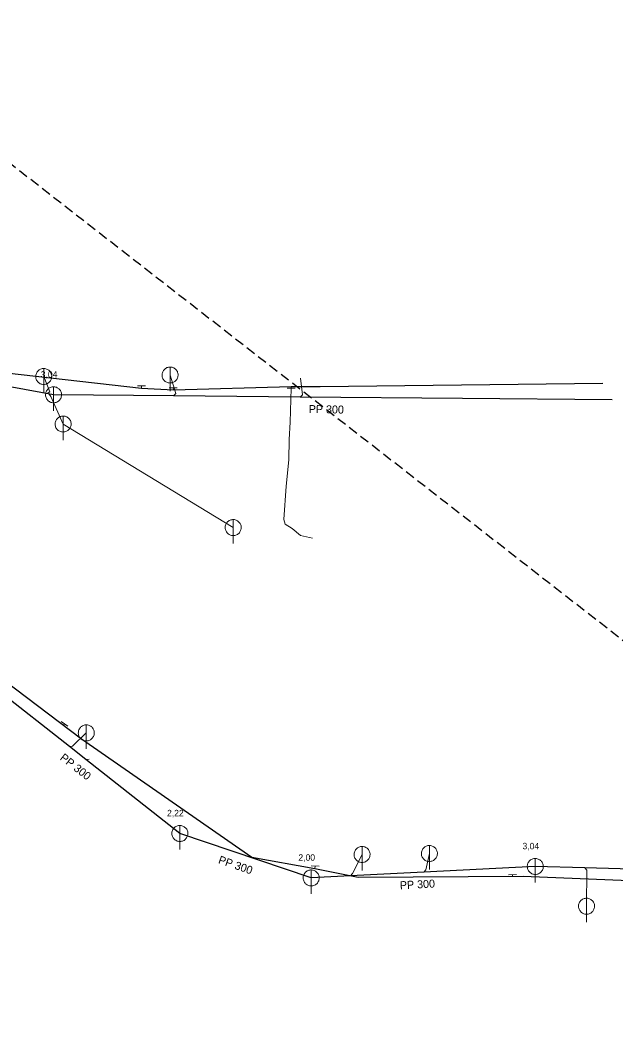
# Model space of a CAD drawing. Extents: x -683466 to -682479, y -996772 to -995963.
# Drawn here: x -683311.7 to -683237.4, y -996087.9 to -995963.2 of the extents above; entities that cross this region are included whole.
import ezdxf

# ---------------------------------------------------------------- set-up
doc = ezdxf.new("R2010")
doc.units = 0
doc.header["$LTSCALE"] = 0.4
doc.linetypes.add('MEDIUM_DASHED', pattern=[4.5, 3, -1.5])
doc.layers.add('1', color=7, linetype='Continuous')
for name, color, linetype, lineweight in [('11', 7, 'Continuous', 13), ('13', 7, 'Continuous', 13), ('14', 7, 'Continuous', 25), ('17', 7, 'Continuous', 25), ('22', 7, 'Continuous', 13), ('34', 7, 'Continuous', 13), ('63', 7, 'MEDIUM_DASHED', 25)]:
    doc.layers.add(name, color=color, linetype=linetype, lineweight=lineweight)

msp = doc.modelspace()

# ---------------------------------------------------------------- linework, layer by layer
at = {"layer": '11'}
msp.add_line((-683285.12, -996026.62), (-683306.359, -996013.69), dxfattribs=at)
for points in [[(-683308.78, -996007.75), (-683308.009, -996009.668), (-683308.342, -996009.895)], [(-683293, -996007.57), (-683292.302, -996009.895), (-683292.588, -996010.175)], [(-683276.719, -996007.96), (-683276.463, -996010.037), (-683276.748, -996010.318)], [(-683306.359, -996013.69), (-683307.879, -996010.27), (-683308.102, -996009.939)], [(-683303.46, -996052.26), (-683305.175, -996053.934), (-683305.57, -996053.982)], [(-683303.109, -996055.561), (-683303.398, -996055.596), (-683303.509, -996055.596)], [(-683269.03, -996067.449), (-683270.223, -996069.84), (-683270.486, -996070.129)], [(-683260.62, -996067.329), (-683261.046, -996069.37), (-683261.307, -996069.66)], [(-683241, -996073.91), (-683240.945, -996069.41), (-683241.213, -996069.127)]]:
    msp.add_lwpolyline(points, dxfattribs=at)
at = {"layer": '13'}
msp.add_lwpolyline([(-683277.891, -996009.221), (-683277.998, -996013.465), (-683278.128, -996015.609), (-683278.178, -996018.154), (-683278.489, -996021.447), (-683278.813, -996025.612), (-683278.612, -996026.183), (-683277.741, -996026.737), (-683276.712, -996027.626), (-683275.231, -996027.926)], dxfattribs=at)
at = {"layer": '14', "lineweight": 13}
for p, q in [((-683296.567, -996009.217), (-683296.559, -996008.92)), ((-683292.577, -996009.418), (-683292.609, -996009.16)), ((-683277.891, -996009.221), (-683277.891, -996009.01)), ((-683306.313, -996051.309), (-683306.18, -996051.12)), ((-683274.899, -996068.89), (-683274.905, -996069.189)), ((-683250.223, -996070.173), (-683250.23, -996069.98))]:
    msp.add_line(p, q, dxfattribs=at)
at = {"layer": '14'}
msp.add_line((-683275.379, -996070.379), (-683291.78, -996064.829), dxfattribs=at)
for points in [[(-683307.55, -996010.039), (-683324.795, -996006.888), (-683328.719, -996006.171), (-683331.359, -996005.69)], [(-683237.8, -996010.67), (-683256.469, -996010.5), (-683276.748, -996010.318), (-683292.588, -996010.175), (-683307.55, -996010.039)], [(-683291.78, -996064.829), (-683303.509, -996055.596), (-683305.57, -996053.982), (-683314.71, -996046.82)], [(-683247.399, -996068.949), (-683261.307, -996069.66), (-683270.486, -996070.129), (-683275.379, -996070.379)], [(-683215.92, -996069.85), (-683225.026, -996069.59), (-683241.213, -996069.127), (-683247.399, -996068.949)]]:
    msp.add_lwpolyline(points, dxfattribs=at)
at = {"layer": '17'}
for points in [[(-683345.871, -996001.145), (-683330.998, -996004.133), (-683319.329, -996006.62), (-683296.567, -996009.217), (-683292.577, -996009.418), (-683277.891, -996009.01), (-683274.249, -996009.008), (-683238.954, -996008.579)], [(-683345.87, -996001.27), (-683340.96, -996022.3), (-683339.832, -996025.943), (-683304.056, -996053.017), (-683282.79, -996067.766), (-683274.905, -996069.189), (-683269.5, -996070.27), (-683248.91, -996070.167), (-683229.542, -996070.96), (-683219.888, -996069.96)]]:
    msp.add_lwpolyline(points, dxfattribs=at)
at = {"layer": '22'}
for p, q in [((-683308.78, -996009.75), (-683308.779, -996006.75)), ((-683293, -996009.57), (-683292.999, -996006.57)), ((-683307.55, -996012.039), (-683307.549, -996009.039)), ((-683306.359, -996015.69), (-683306.358, -996012.69)), ((-683285.12, -996028.62), (-683285.119, -996025.62)), ((-683303.46, -996054.26), (-683303.459, -996051.26)), ((-683291.78, -996066.829), (-683291.779, -996063.829)), ((-683269.03, -996069.449), (-683269.029, -996066.449)), ((-683260.62, -996069.329), (-683260.619, -996066.329)), ((-683247.399, -996070.949), (-683247.398, -996067.949)), ((-683275.379, -996072.379), (-683275.378, -996069.379)), ((-683241, -996075.91), (-683240.999, -996072.91))]:
    msp.add_line(p, q, dxfattribs=at)
for points in [[(-683307.78, -996007.75), (-683307.785, -996007.641), (-683307.803, -996007.533), (-683307.833, -996007.427), (-683307.873, -996007.326), (-683307.925, -996007.229), (-683307.987, -996007.139), (-683308.059, -996007.056), (-683308.139, -996006.982), (-683308.227, -996006.916), (-683308.321, -996006.861), (-683308.421, -996006.816), (-683308.526, -996006.783), (-683308.633, -996006.761), (-683308.742, -996006.751), (-683308.852, -996006.753), (-683308.96, -996006.767), (-683309.067, -996006.792), (-683309.17, -996006.829), (-683309.268, -996006.878), (-683309.36, -996006.936), (-683309.446, -996007.005), (-683309.523, -996007.082), (-683309.592, -996007.168), (-683309.651, -996007.26), (-683309.699, -996007.358), (-683309.736, -996007.461), (-683309.762, -996007.568), (-683309.776, -996007.676), (-683309.779, -996007.786), (-683309.769, -996007.895), (-683309.748, -996008.002), (-683309.714, -996008.106), (-683309.67, -996008.206), (-683309.615, -996008.301), (-683309.549, -996008.389), (-683309.475, -996008.469), (-683309.392, -996008.541), (-683309.302, -996008.603), (-683309.206, -996008.655), (-683309.104, -996008.696), (-683308.999, -996008.726), (-683308.891, -996008.744), (-683308.781, -996008.75), (-683308.672, -996008.744), (-683308.564, -996008.726), (-683308.459, -996008.697), (-683308.357, -996008.656), (-683308.26, -996008.604), (-683308.17, -996008.542), (-683308.087, -996008.471), (-683308.012, -996008.391), (-683307.947, -996008.303), (-683307.891, -996008.209), (-683307.847, -996008.109), (-683307.813, -996008.005), (-683307.791, -996007.897), (-683307.781, -996007.788)], [(-683292, -996007.57), (-683292.005, -996007.461), (-683292.023, -996007.353), (-683292.053, -996007.247), (-683292.093, -996007.146), (-683292.145, -996007.049), (-683292.207, -996006.959), (-683292.279, -996006.876), (-683292.359, -996006.802), (-683292.447, -996006.736), (-683292.541, -996006.681), (-683292.641, -996006.636), (-683292.746, -996006.603), (-683292.853, -996006.581), (-683292.962, -996006.571), (-683293.072, -996006.573), (-683293.18, -996006.587), (-683293.287, -996006.612), (-683293.39, -996006.649), (-683293.488, -996006.698), (-683293.58, -996006.756), (-683293.666, -996006.825), (-683293.743, -996006.902), (-683293.812, -996006.988), (-683293.871, -996007.08), (-683293.919, -996007.178), (-683293.956, -996007.281), (-683293.982, -996007.388), (-683293.996, -996007.496), (-683293.999, -996007.606), (-683293.989, -996007.715), (-683293.968, -996007.822), (-683293.934, -996007.926), (-683293.89, -996008.026), (-683293.835, -996008.121), (-683293.769, -996008.209), (-683293.695, -996008.289), (-683293.612, -996008.361), (-683293.522, -996008.423), (-683293.426, -996008.475), (-683293.324, -996008.516), (-683293.219, -996008.546), (-683293.111, -996008.564), (-683293.001, -996008.57), (-683292.892, -996008.564), (-683292.784, -996008.546), (-683292.679, -996008.517), (-683292.577, -996008.476), (-683292.48, -996008.424), (-683292.39, -996008.362), (-683292.307, -996008.291), (-683292.232, -996008.211), (-683292.167, -996008.123), (-683292.111, -996008.029), (-683292.067, -996007.929), (-683292.033, -996007.825), (-683292.011, -996007.717), (-683292.001, -996007.608)], [(-683306.55, -996010.039), (-683306.555, -996009.93), (-683306.573, -996009.822), (-683306.603, -996009.716), (-683306.643, -996009.615), (-683306.695, -996009.518), (-683306.757, -996009.428), (-683306.829, -996009.345), (-683306.909, -996009.271), (-683306.997, -996009.205), (-683307.091, -996009.15), (-683307.191, -996009.105), (-683307.296, -996009.072), (-683307.403, -996009.05), (-683307.512, -996009.04), (-683307.622, -996009.042), (-683307.73, -996009.056), (-683307.837, -996009.081), (-683307.94, -996009.118), (-683308.038, -996009.167), (-683308.13, -996009.225), (-683308.216, -996009.294), (-683308.293, -996009.371), (-683308.362, -996009.457), (-683308.421, -996009.549), (-683308.469, -996009.647), (-683308.506, -996009.75), (-683308.532, -996009.857), (-683308.546, -996009.965), (-683308.549, -996010.075), (-683308.539, -996010.184), (-683308.518, -996010.291), (-683308.484, -996010.395), (-683308.44, -996010.495), (-683308.385, -996010.59), (-683308.319, -996010.678), (-683308.245, -996010.758), (-683308.162, -996010.83), (-683308.072, -996010.892), (-683307.976, -996010.944), (-683307.874, -996010.985), (-683307.769, -996011.015), (-683307.661, -996011.033), (-683307.551, -996011.039), (-683307.442, -996011.033), (-683307.334, -996011.015), (-683307.229, -996010.986), (-683307.127, -996010.945), (-683307.03, -996010.893), (-683306.94, -996010.831), (-683306.857, -996010.76), (-683306.782, -996010.68), (-683306.717, -996010.592), (-683306.661, -996010.498), (-683306.617, -996010.398), (-683306.583, -996010.294), (-683306.561, -996010.186), (-683306.551, -996010.077)], [(-683305.359, -996013.69), (-683305.364, -996013.581), (-683305.382, -996013.473), (-683305.412, -996013.367), (-683305.452, -996013.266), (-683305.504, -996013.169), (-683305.566, -996013.079), (-683305.638, -996012.996), (-683305.718, -996012.922), (-683305.806, -996012.856), (-683305.9, -996012.801), (-683306, -996012.756), (-683306.105, -996012.723), (-683306.212, -996012.701), (-683306.321, -996012.691), (-683306.431, -996012.693), (-683306.539, -996012.707), (-683306.646, -996012.732), (-683306.749, -996012.769), (-683306.847, -996012.818), (-683306.939, -996012.876), (-683307.025, -996012.945), (-683307.102, -996013.022), (-683307.171, -996013.108), (-683307.23, -996013.2), (-683307.278, -996013.298), (-683307.315, -996013.401), (-683307.341, -996013.508), (-683307.355, -996013.616), (-683307.358, -996013.726), (-683307.348, -996013.835), (-683307.327, -996013.942), (-683307.293, -996014.046), (-683307.249, -996014.146), (-683307.194, -996014.241), (-683307.128, -996014.329), (-683307.054, -996014.409), (-683306.971, -996014.481), (-683306.881, -996014.543), (-683306.785, -996014.595), (-683306.683, -996014.636), (-683306.578, -996014.666), (-683306.47, -996014.684), (-683306.36, -996014.69), (-683306.251, -996014.684), (-683306.143, -996014.666), (-683306.038, -996014.637), (-683305.936, -996014.596), (-683305.839, -996014.544), (-683305.749, -996014.482), (-683305.666, -996014.411), (-683305.591, -996014.331), (-683305.526, -996014.243), (-683305.47, -996014.149), (-683305.426, -996014.049), (-683305.392, -996013.945), (-683305.37, -996013.837), (-683305.36, -996013.728)], [(-683284.12, -996026.62), (-683284.125, -996026.511), (-683284.143, -996026.403), (-683284.173, -996026.297), (-683284.213, -996026.196), (-683284.265, -996026.099), (-683284.327, -996026.009), (-683284.399, -996025.926), (-683284.479, -996025.852), (-683284.567, -996025.786), (-683284.661, -996025.731), (-683284.761, -996025.686), (-683284.866, -996025.653), (-683284.973, -996025.631), (-683285.082, -996025.621), (-683285.192, -996025.623), (-683285.3, -996025.637), (-683285.407, -996025.662), (-683285.51, -996025.699), (-683285.608, -996025.748), (-683285.7, -996025.806), (-683285.786, -996025.875), (-683285.863, -996025.952), (-683285.932, -996026.038), (-683285.991, -996026.13), (-683286.039, -996026.228), (-683286.076, -996026.331), (-683286.102, -996026.438), (-683286.116, -996026.546), (-683286.119, -996026.656), (-683286.109, -996026.765), (-683286.088, -996026.872), (-683286.054, -996026.976), (-683286.01, -996027.076), (-683285.955, -996027.171), (-683285.889, -996027.259), (-683285.815, -996027.339), (-683285.732, -996027.411), (-683285.642, -996027.473), (-683285.546, -996027.525), (-683285.444, -996027.566), (-683285.339, -996027.596), (-683285.231, -996027.614), (-683285.121, -996027.62), (-683285.012, -996027.614), (-683284.904, -996027.596), (-683284.799, -996027.567), (-683284.697, -996027.526), (-683284.6, -996027.474), (-683284.51, -996027.412), (-683284.427, -996027.341), (-683284.352, -996027.261), (-683284.287, -996027.173), (-683284.231, -996027.079), (-683284.187, -996026.979), (-683284.153, -996026.875), (-683284.131, -996026.767), (-683284.121, -996026.658)], [(-683302.46, -996052.26), (-683302.465, -996052.151), (-683302.483, -996052.043), (-683302.513, -996051.937), (-683302.553, -996051.836), (-683302.605, -996051.739), (-683302.667, -996051.649), (-683302.739, -996051.566), (-683302.819, -996051.492), (-683302.907, -996051.426), (-683303.001, -996051.371), (-683303.101, -996051.326), (-683303.206, -996051.293), (-683303.313, -996051.271), (-683303.422, -996051.261), (-683303.532, -996051.263), (-683303.64, -996051.277), (-683303.747, -996051.302), (-683303.85, -996051.339), (-683303.948, -996051.388), (-683304.04, -996051.446), (-683304.126, -996051.515), (-683304.203, -996051.592), (-683304.272, -996051.678), (-683304.331, -996051.77), (-683304.379, -996051.868), (-683304.416, -996051.971), (-683304.442, -996052.078), (-683304.456, -996052.186), (-683304.459, -996052.296), (-683304.449, -996052.405), (-683304.428, -996052.512), (-683304.394, -996052.616), (-683304.35, -996052.716), (-683304.295, -996052.811), (-683304.229, -996052.899), (-683304.155, -996052.979), (-683304.072, -996053.051), (-683303.982, -996053.113), (-683303.886, -996053.165), (-683303.784, -996053.206), (-683303.679, -996053.236), (-683303.571, -996053.254), (-683303.461, -996053.26), (-683303.352, -996053.254), (-683303.244, -996053.236), (-683303.139, -996053.207), (-683303.037, -996053.166), (-683302.94, -996053.114), (-683302.85, -996053.052), (-683302.767, -996052.981), (-683302.692, -996052.901), (-683302.627, -996052.813), (-683302.571, -996052.719), (-683302.527, -996052.619), (-683302.493, -996052.515), (-683302.471, -996052.407), (-683302.461, -996052.298)], [(-683290.78, -996064.829), (-683290.785, -996064.72), (-683290.803, -996064.612), (-683290.833, -996064.506), (-683290.873, -996064.405), (-683290.925, -996064.308), (-683290.987, -996064.218), (-683291.059, -996064.135), (-683291.139, -996064.061), (-683291.227, -996063.995), (-683291.321, -996063.94), (-683291.421, -996063.895), (-683291.526, -996063.862), (-683291.633, -996063.84), (-683291.742, -996063.83), (-683291.852, -996063.832), (-683291.96, -996063.846), (-683292.067, -996063.871), (-683292.17, -996063.908), (-683292.268, -996063.957), (-683292.36, -996064.015), (-683292.446, -996064.084), (-683292.523, -996064.161), (-683292.592, -996064.247), (-683292.651, -996064.339), (-683292.699, -996064.437), (-683292.736, -996064.54), (-683292.762, -996064.647), (-683292.776, -996064.755), (-683292.779, -996064.865), (-683292.769, -996064.974), (-683292.748, -996065.081), (-683292.714, -996065.185), (-683292.67, -996065.285), (-683292.615, -996065.38), (-683292.549, -996065.468), (-683292.475, -996065.548), (-683292.392, -996065.62), (-683292.302, -996065.682), (-683292.206, -996065.734), (-683292.104, -996065.775), (-683291.999, -996065.805), (-683291.891, -996065.823), (-683291.781, -996065.829), (-683291.672, -996065.823), (-683291.564, -996065.805), (-683291.459, -996065.776), (-683291.357, -996065.735), (-683291.26, -996065.683), (-683291.17, -996065.621), (-683291.087, -996065.55), (-683291.012, -996065.47), (-683290.947, -996065.382), (-683290.891, -996065.288), (-683290.847, -996065.188), (-683290.813, -996065.084), (-683290.791, -996064.976), (-683290.781, -996064.867)], [(-683268.03, -996067.449), (-683268.035, -996067.34), (-683268.053, -996067.232), (-683268.083, -996067.126), (-683268.123, -996067.025), (-683268.175, -996066.928), (-683268.237, -996066.838), (-683268.309, -996066.755), (-683268.389, -996066.681), (-683268.477, -996066.615), (-683268.571, -996066.56), (-683268.671, -996066.515), (-683268.776, -996066.482), (-683268.883, -996066.46), (-683268.992, -996066.45), (-683269.102, -996066.452), (-683269.21, -996066.466), (-683269.317, -996066.491), (-683269.42, -996066.528), (-683269.518, -996066.577), (-683269.61, -996066.635), (-683269.696, -996066.704), (-683269.773, -996066.781), (-683269.842, -996066.867), (-683269.901, -996066.959), (-683269.949, -996067.057), (-683269.986, -996067.16), (-683270.012, -996067.267), (-683270.026, -996067.375), (-683270.029, -996067.485), (-683270.019, -996067.594), (-683269.998, -996067.701), (-683269.964, -996067.805), (-683269.92, -996067.905), (-683269.865, -996068), (-683269.799, -996068.088), (-683269.725, -996068.168), (-683269.642, -996068.24), (-683269.552, -996068.302), (-683269.456, -996068.354), (-683269.354, -996068.395), (-683269.249, -996068.425), (-683269.141, -996068.443), (-683269.031, -996068.449), (-683268.922, -996068.443), (-683268.814, -996068.425), (-683268.709, -996068.396), (-683268.607, -996068.355), (-683268.51, -996068.303), (-683268.42, -996068.241), (-683268.337, -996068.17), (-683268.262, -996068.09), (-683268.197, -996068.002), (-683268.141, -996067.908), (-683268.097, -996067.808), (-683268.063, -996067.704), (-683268.041, -996067.596), (-683268.031, -996067.487)], [(-683259.62, -996067.329), (-683259.625, -996067.22), (-683259.643, -996067.112), (-683259.673, -996067.006), (-683259.713, -996066.905), (-683259.765, -996066.808), (-683259.827, -996066.718), (-683259.899, -996066.635), (-683259.979, -996066.561), (-683260.067, -996066.495), (-683260.161, -996066.44), (-683260.261, -996066.395), (-683260.366, -996066.362), (-683260.473, -996066.34), (-683260.582, -996066.33), (-683260.692, -996066.332), (-683260.8, -996066.346), (-683260.907, -996066.371), (-683261.01, -996066.408), (-683261.108, -996066.457), (-683261.2, -996066.515), (-683261.286, -996066.584), (-683261.363, -996066.661), (-683261.432, -996066.747), (-683261.491, -996066.839), (-683261.539, -996066.937), (-683261.576, -996067.04), (-683261.602, -996067.147), (-683261.616, -996067.255), (-683261.619, -996067.365), (-683261.609, -996067.474), (-683261.588, -996067.581), (-683261.554, -996067.685), (-683261.51, -996067.785), (-683261.455, -996067.88), (-683261.389, -996067.968), (-683261.315, -996068.048), (-683261.232, -996068.12), (-683261.142, -996068.182), (-683261.046, -996068.234), (-683260.944, -996068.275), (-683260.839, -996068.305), (-683260.731, -996068.323), (-683260.621, -996068.329), (-683260.512, -996068.323), (-683260.404, -996068.305), (-683260.299, -996068.276), (-683260.197, -996068.235), (-683260.1, -996068.183), (-683260.01, -996068.121), (-683259.927, -996068.05), (-683259.852, -996067.97), (-683259.787, -996067.882), (-683259.731, -996067.788), (-683259.687, -996067.688), (-683259.653, -996067.584), (-683259.631, -996067.476), (-683259.621, -996067.367)], [(-683246.399, -996068.949), (-683246.404, -996068.84), (-683246.422, -996068.732), (-683246.452, -996068.626), (-683246.492, -996068.525), (-683246.544, -996068.428), (-683246.606, -996068.338), (-683246.678, -996068.255), (-683246.758, -996068.181), (-683246.846, -996068.115), (-683246.94, -996068.06), (-683247.04, -996068.015), (-683247.145, -996067.982), (-683247.252, -996067.96), (-683247.361, -996067.95), (-683247.471, -996067.952), (-683247.579, -996067.966), (-683247.686, -996067.991), (-683247.789, -996068.028), (-683247.887, -996068.077), (-683247.979, -996068.135), (-683248.065, -996068.204), (-683248.142, -996068.281), (-683248.211, -996068.367), (-683248.27, -996068.459), (-683248.318, -996068.557), (-683248.355, -996068.66), (-683248.381, -996068.767), (-683248.395, -996068.875), (-683248.398, -996068.985), (-683248.388, -996069.094), (-683248.367, -996069.201), (-683248.333, -996069.305), (-683248.289, -996069.405), (-683248.234, -996069.5), (-683248.168, -996069.588), (-683248.094, -996069.668), (-683248.011, -996069.74), (-683247.921, -996069.802), (-683247.825, -996069.854), (-683247.723, -996069.895), (-683247.618, -996069.925), (-683247.51, -996069.943), (-683247.4, -996069.949), (-683247.291, -996069.943), (-683247.183, -996069.925), (-683247.078, -996069.896), (-683246.976, -996069.855), (-683246.879, -996069.803), (-683246.789, -996069.741), (-683246.706, -996069.67), (-683246.631, -996069.59), (-683246.566, -996069.502), (-683246.51, -996069.408), (-683246.466, -996069.308), (-683246.432, -996069.204), (-683246.41, -996069.096), (-683246.4, -996068.987)], [(-683274.379, -996070.379), (-683274.384, -996070.27), (-683274.402, -996070.162), (-683274.432, -996070.056), (-683274.472, -996069.955), (-683274.524, -996069.858), (-683274.586, -996069.768), (-683274.658, -996069.685), (-683274.738, -996069.611), (-683274.826, -996069.545), (-683274.92, -996069.49), (-683275.02, -996069.445), (-683275.125, -996069.412), (-683275.232, -996069.39), (-683275.341, -996069.38), (-683275.451, -996069.382), (-683275.559, -996069.396), (-683275.666, -996069.421), (-683275.769, -996069.458), (-683275.867, -996069.507), (-683275.959, -996069.565), (-683276.045, -996069.634), (-683276.122, -996069.711), (-683276.191, -996069.797), (-683276.25, -996069.889), (-683276.298, -996069.987), (-683276.335, -996070.09), (-683276.361, -996070.197), (-683276.375, -996070.305), (-683276.378, -996070.415), (-683276.368, -996070.524), (-683276.347, -996070.631), (-683276.313, -996070.735), (-683276.269, -996070.835), (-683276.214, -996070.93), (-683276.148, -996071.018), (-683276.074, -996071.098), (-683275.991, -996071.17), (-683275.901, -996071.232), (-683275.805, -996071.284), (-683275.703, -996071.325), (-683275.598, -996071.355), (-683275.49, -996071.373), (-683275.38, -996071.379), (-683275.271, -996071.373), (-683275.163, -996071.355), (-683275.058, -996071.326), (-683274.956, -996071.285), (-683274.859, -996071.233), (-683274.769, -996071.171), (-683274.686, -996071.1), (-683274.611, -996071.02), (-683274.546, -996070.932), (-683274.49, -996070.838), (-683274.446, -996070.738), (-683274.412, -996070.634), (-683274.39, -996070.526), (-683274.38, -996070.417)], [(-683240, -996073.91), (-683240.005, -996073.801), (-683240.023, -996073.693), (-683240.053, -996073.587), (-683240.093, -996073.486), (-683240.145, -996073.389), (-683240.207, -996073.299), (-683240.279, -996073.216), (-683240.359, -996073.142), (-683240.447, -996073.076), (-683240.541, -996073.021), (-683240.641, -996072.976), (-683240.746, -996072.943), (-683240.853, -996072.921), (-683240.962, -996072.911), (-683241.072, -996072.913), (-683241.18, -996072.927), (-683241.287, -996072.952), (-683241.39, -996072.989), (-683241.488, -996073.038), (-683241.58, -996073.096), (-683241.666, -996073.165), (-683241.743, -996073.242), (-683241.812, -996073.328), (-683241.871, -996073.42), (-683241.919, -996073.518), (-683241.956, -996073.621), (-683241.982, -996073.728), (-683241.996, -996073.836), (-683241.999, -996073.946), (-683241.989, -996074.055), (-683241.968, -996074.162), (-683241.934, -996074.266), (-683241.89, -996074.366), (-683241.835, -996074.461), (-683241.769, -996074.549), (-683241.695, -996074.629), (-683241.612, -996074.701), (-683241.522, -996074.763), (-683241.426, -996074.815), (-683241.324, -996074.856), (-683241.219, -996074.886), (-683241.111, -996074.904), (-683241.001, -996074.91), (-683240.892, -996074.904), (-683240.784, -996074.886), (-683240.679, -996074.857), (-683240.577, -996074.816), (-683240.48, -996074.764), (-683240.39, -996074.702), (-683240.307, -996074.631), (-683240.232, -996074.551), (-683240.167, -996074.463), (-683240.111, -996074.369), (-683240.067, -996074.269), (-683240.033, -996074.165), (-683240.011, -996074.057), (-683240.001, -996073.948)]]:
    msp.add_lwpolyline(points, close=True, dxfattribs=at)
at = {"layer": '34'}
for p, q in [((-683296.059, -996008.915), (-683297.058, -996008.923)), ((-683292.109, -996009.155), (-683293.108, -996009.163)), ((-683277.391, -996009.216), (-683278.39, -996009.224)), ((-683306.588, -996050.832), (-683305.771, -996051.408)), ((-683274.399, -996068.899), (-683275.398, -996068.879)), ((-683250.729, -996069.997), (-683249.73, -996069.963))]:
    msp.add_line(p, q, dxfattribs=at)
at = {"layer": '63'}
msp.add_lwpolyline([(-683425.281, -996021.839), (-683425.281, -996016.256), (-683425.281, -996016.256), (-683335.962, -995963.223), (-683335.962, -995963.223), (-682479.059, -996630.324), (-682479.059, -996630.324), (-682551.631, -996711.269), (-682551.631, -996711.269), (-683416.907, -996083.246), (-683416.907, -996083.246)], close=True, dxfattribs=at)

# ---------------------------------------------------------------- texts
at = {"layer": '1'}
for s, p in [('3,04', (-683309.15, -996007.887)), ('2,22', (-683293.38, -996062.677)), ('3,04', (-683249, -996066.797)), ('2,00', (-683276.979, -996068.227))]:
    msp.add_text(s, height=0.8, dxfattribs=at).set_placement(p)
for rotation, p in [(359, (-683275.692, -996012.312)), (322, (-683306.83, -996055.533)), (341, (-683287.057, -996068.522)), (3, (-683264.284, -996071.8))]:
    msp.add_text('PP 300', height=1, rotation=rotation, dxfattribs=at).set_placement(p)

doc.saveas('drawing.dxf')
